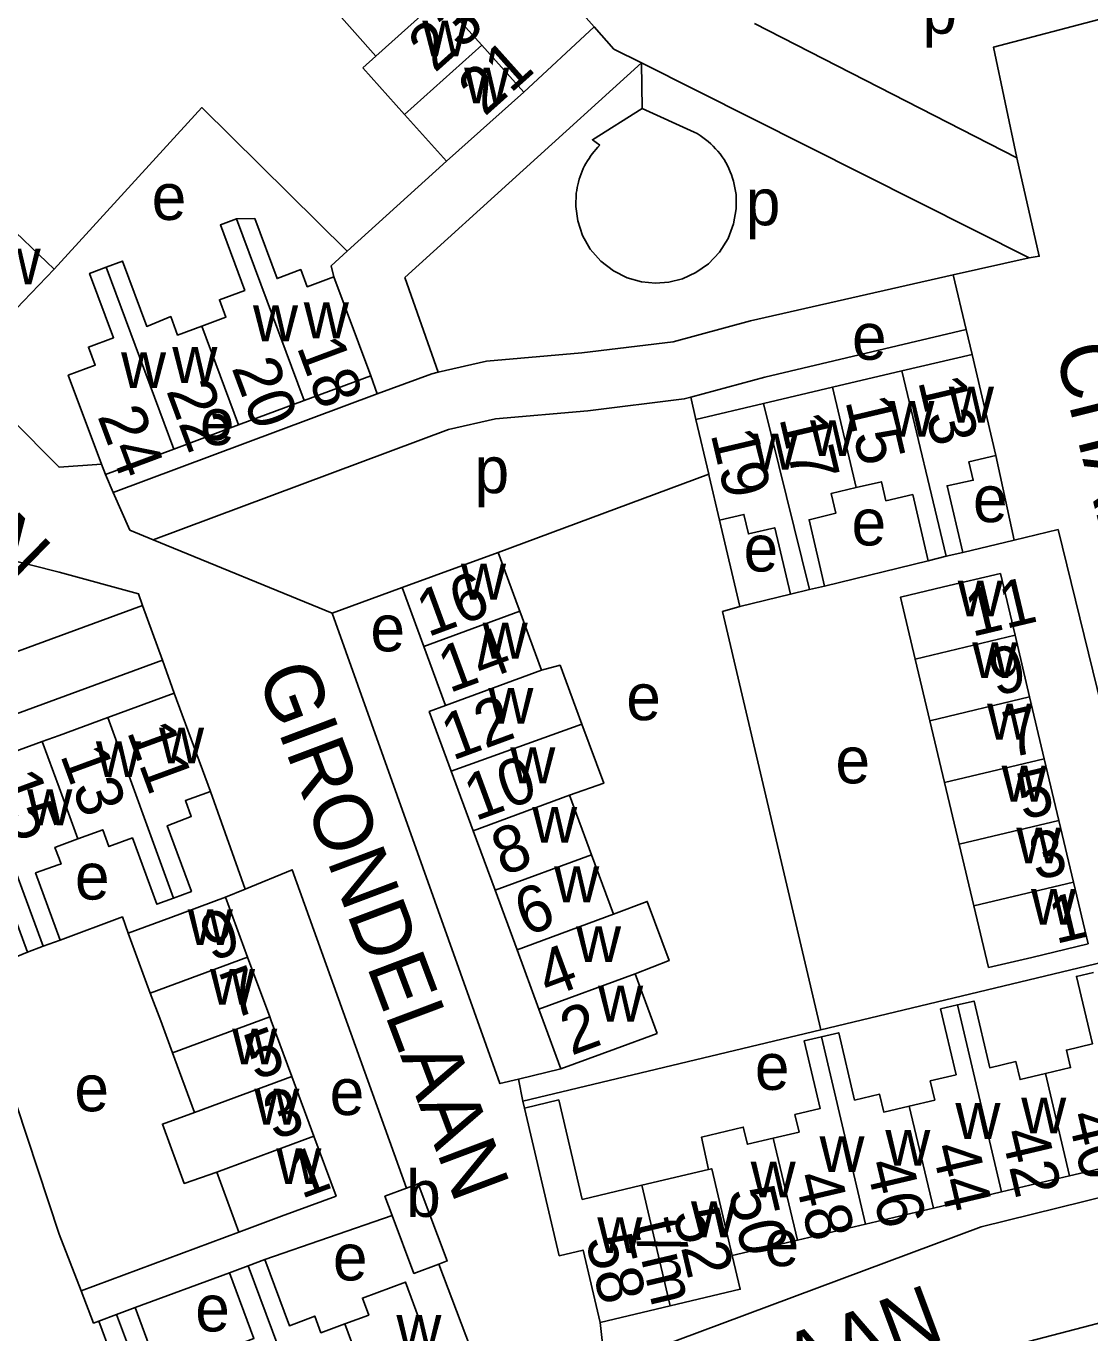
# Model space of a CAD drawing. Extents: x 157768 to 159790, y 387230 to 389604.
# Drawn here: x 159097.2 to 159188.5, y 388723.2 to 388835.4 of the extents above; entities that cross this region are included whole.
import ezdxf

# ---------------------------------------------------------------- set-up
doc = ezdxf.new("R2010")
doc.units = 0
for name, color, linetype in [('BLT_Basislijn', 7, 'Continuous'), ('BLT_Bebouwing', 7, 'Continuous'), ('BLT_Centroide', 7, 'Continuous'), ('BLT_Huisnummer', 7, 'Continuous'), ('BLT_Huisnummer_ tussenligend', 7, 'Continuous'), ('BLT_Huisnummer_reeks', 7, 'Continuous'), ('BLT_Onderverdeling_panden', 7, 'Continuous'), ('BLT_Straatnaam', 7, 'Continuous'), ('BLT_Vlakafsluiter', 7, 'Continuous')]:
    doc.layers.add(name, color=color, linetype=linetype)

msp = doc.modelspace()

# ---------------------------------------------------------------- linework, layer by layer
at = {"layer": 'BLT_Basislijn'}
for p, q in [((159139.9, 388829.78), (159145.94, 388835.4)), ((159145.94, 388835.4), (159147.65, 388833.48)), ((159182.23, 388824.14), (159159.73, 388835.67)), ((159147.65, 388833.48), (159150.03, 388832.28)), ((159150.03, 388832.28), (159129.7, 388813.85)), ((159150.03, 388832.28), (159183.31, 388815.54)), ((159150.06, 388828.37), (159154.55, 388826.35)), ((159133.27, 388823.84), (159124.75, 388816.12)), ((159176.78, 388814.07), (159177.9, 388809.4)), ((159129.7, 388813.85), (159132.55, 388805.72)), ((159177.9, 388809.4), (159178.41, 388807.25)), ((159126.78, 388805.42), (159127.33, 388803.85)), ((159104.66, 388795.39), (159127.33, 388803.85)), ((159154.68, 388801.66), (159154.25, 388803.57)), ((159182.01, 388791.29), (159180.45, 388798.57)), ((159104.66, 388795.39), (159103.98, 388796.93)), ((159155.79, 388796.96), (159137.71, 388790.24)), ((159106.09, 388792.16), (159104.66, 388795.39)), ((159156.71, 388793.01), (159158.46, 388785.59)), ((159108.08, 388791.33), (159106.09, 388792.16)), ((159123.45, 388785.01), (159108.08, 388791.33)), ((159123.45, 388785.01), (159129.46, 388787.21)), ((159158.46, 388785.59), (159156.97, 388785.17)), ((159165.41, 388749.22), (159156.97, 388785.17)), ((159115.98, 388761.31), (159113, 388769.71)), ((159115.98, 388761.31), (159114.29, 388760.61)), ((159092.63, 388753.97), (159097.3, 388755.91)), ((159194.59, 388756.22), (159165.41, 388749.22)), ((159165.41, 388749.22), (159139.84, 388743.09)), ((159143.1, 388745.87), (159139.45, 388744.99)), ((159139.84, 388743.09), (159139.45, 388744.99)), ((159139.84, 388743.09), (159139.96, 388742.5)), ((159101.9, 388726.8), (159115.44, 388731.86)), ((159106.53, 388725.37), (159114.63, 388728.36))]:
    msp.add_line(p, q, dxfattribs=at)
for points in [[(159115.59, 388866.68), (159116.98, 388868.02), (159145.94, 388835.4)], [(159182.23, 388824.14), (159180.25, 388833.65), (159199.41, 388838.71), (159195.8, 388853.99), (159195.38, 388858.13), (159196.26, 388858.38)], [(159124.75, 388816.12), (159112.27, 388828.45), (159099.59, 388814.57)], [(159146.44, 388825.21), (159145.8, 388825.68), (159150.06, 388828.37)], [(159154.55, 388826.35), (159154.8, 388826.21), (159155.04, 388826.06), (159155.28, 388825.89), (159155.51, 388825.72), (159155.74, 388825.54), (159155.96, 388825.34), (159156.17, 388825.13), (159156.38, 388824.92), (159156.57, 388824.7), (159156.76, 388824.47), (159156.93, 388824.23), (159157.1, 388823.98), (159157.25, 388823.73), (159157.39, 388823.47), (159157.52, 388823.21), (159157.64, 388822.94), (159157.74, 388822.67), (159157.84, 388822.4), (159157.92, 388822.13)], [(159144.41, 388821.1), (159144.45, 388821.34), (159144.49, 388821.58), (159144.54, 388821.82), (159144.6, 388822.05), (159144.66, 388822.29), (159144.74, 388822.53), (159144.83, 388822.76), (159144.92, 388822.99), (159145.02, 388823.21), (159145.13, 388823.44), (159145.25, 388823.66), (159145.37, 388823.87), (159145.51, 388824.08), (159145.64, 388824.28), (159145.79, 388824.48), (159145.94, 388824.67), (159146.1, 388824.86), (159146.27, 388825.04), (159146.44, 388825.21)], [(159182.23, 388824.14), (159184.17, 388815.68), (159183.31, 388815.54)], [(159157.92, 388822.13), (159158.14, 388820.98), (159158.15, 388819.74), (159157.93, 388818.45), (159157.45, 388817.19), (159156.72, 388816.03), (159155.78, 388815.04), (159154.69, 388814.27), (159153.53, 388813.75), (159152.36, 388813.45), (159151.22, 388813.36), (159150.02, 388813.48), (159148.79, 388813.83), (159147.6, 388814.42), (159146.52, 388815.26), (159145.62, 388816.29), (159144.96, 388817.47), (159144.54, 388818.71), (159144.37, 388819.94), (159144.41, 388821.1)], [(159124.75, 388816.12), (159123.36, 388814.85), (159123.61, 388813.92)], [(159176.78, 388814.07), (159183.31, 388815.54)], [(159132.55, 388805.72), (159136.71, 388806.66), (159144.89, 388807.37), (159152.73, 388808.34), (159159.37, 388810.14), (159176.78, 388814.07)], [(159154.25, 388803.57), (159160.61, 388805.29), (159177.9, 388809.4)], [(159091.65, 388805.96), (159100.01, 388797.56), (159103.65, 388797.81)], [(159127.33, 388803.85), (159132, 388805.59), (159132.55, 388805.72)], [(159108.08, 388791.33), (159133.43, 388800.79), (159137.49, 388801.7), (159145.42, 388802.4), (159153.69, 388803.42), (159154.25, 388803.57)], [(159081.96, 388797.39), (159082.25, 388797.1), (159088.23, 388791.52), (159100, 388788.53), (159106.82, 388786.69), (159107.18, 388785.69)], [(159182.01, 388791.29), (159185.78, 388792.2), (159193.94, 388758.92), (159194.59, 388756.22)], [(159182.01, 388791.29), (159177.6, 388790.22)], [(159174.64, 388789.52), (159165.74, 388787.35)], [(159162.8, 388786.65), (159158.46, 388785.59)], [(159055.01, 388748.76), (159081.59, 388776.28), (159107.18, 388785.69)], [(159107.18, 388785.69), (159108.88, 388780.99)], [(159123.45, 388785.01), (159137.86, 388744.61), (159139.45, 388744.99)], [(159086.04, 388772.59), (159108.88, 388780.99)], [(159108.88, 388780.99), (159109.9, 388778.16)], [(159129.85, 388735.63), (159120.03, 388762.98), (159115.98, 388761.31)], [(159100.11, 388756.94), (159105.45, 388758.93), (159105.94, 388757.53)], [(159101.9, 388726.8), (159100, 388731.68), (159092.63, 388753.97)], [(159146.47, 388724.1), (159146.89, 388720.24), (159179.17, 388732.29), (159199.12, 388737.23)], [(159117.67, 388729.49), (159128.6, 388733.28)], [(159177.3, 388720.26), (159183.37, 388722.48), (159194.31, 388725.35), (159218.67, 388731.21), (159223.12, 388732.06), (159225.89, 388732.25), (159227.5, 388731.47), (159228.51, 388730.05), (159232.95, 388710.61), (159233.22, 388709.41)], [(159133.4, 388717.7), (159136.44, 388718.96), (159132.62, 388729.1)], [(159101.9, 388726.8), (159102.97, 388724.04), (159103.41, 388724.21)]]:
    msp.add_lwpolyline(points, dxfattribs=at)
at = {"layer": 'BLT_Bebouwing'}
for p, q in [((159136.31, 388833.8), (159132.71, 388837.81)), ((159127.21, 388832.88), (159123.36, 388837.18)), ((159136.31, 388833.8), (159139.9, 388829.78)), ((159126.08, 388831.87), (159127.21, 388832.88)), ((159129.67, 388827.85), (159126.08, 388831.87)), ((159139.9, 388829.78), (159133.27, 388823.84)), ((159099.59, 388814.57), (159095.64, 388818.35)), ((159123.61, 388813.92), (159126.78, 388805.42)), ((159178.41, 388807.25), (159172.36, 388805.83)), ((159180.45, 388798.57), (159178.41, 388807.25)), ((159126.78, 388805.42), (159121.06, 388803.29)), ((159172.36, 388805.83), (159166.43, 388804.43)), ((159166.43, 388804.43), (159160.49, 388803.03)), ((159115.42, 388801.19), (159121.06, 388803.29)), ((159160.49, 388803.03), (159154.68, 388801.66)), ((159154.68, 388801.66), (159155.79, 388796.96)), ((159109.86, 388799.12), (159115.42, 388801.19)), ((159103.98, 388796.93), (159109.86, 388799.12)), ((159103.65, 388797.81), (159103.98, 388796.93)), ((159129.46, 388787.21), (159137.71, 388790.24)), ((159131.33, 388782.15), (159129.46, 388787.21)), ((159139.57, 388785.18), (159141.43, 388780.12)), ((159183.34, 388777.82), (159182.09, 388783.12)), ((159133.2, 388777.08), (159131.33, 388782.15)), ((159174.77, 388775.78), (159173.51, 388781.08)), ((159109.9, 388778.16), (159104.19, 388776.06)), ((159113, 388769.71), (159109.9, 388778.16)), ((159184.6, 388772.52), (159183.34, 388777.82)), ((159176.02, 388770.48), (159174.77, 388775.78)), ((159098.55, 388773.99), (159092.92, 388771.92)), ((159185.86, 388767.21), (159184.6, 388772.52)), ((159135.56, 388766.33), (159133.68, 388771.45)), ((159177.28, 388765.18), (159176.02, 388770.48)), ((159143.83, 388769.38), (159145.71, 388764.26)), ((159187.12, 388761.91), (159185.86, 388767.21)), ((159137.44, 388761.22), (159135.56, 388766.33)), ((159178.54, 388759.88), (159177.28, 388765.18)), ((159145.71, 388764.26), (159147.6, 388759.15)), ((159139.33, 388756.1), (159137.44, 388761.22)), ((159188.38, 388756.61), (159187.12, 388761.91)), ((159116.19, 388755.48), (159114.29, 388760.61)), ((159179.8, 388754.57), (159178.54, 388759.88)), ((159098.63, 388756.4), (159100.11, 388756.94)), ((159107.84, 388752.39), (159105.94, 388757.53)), ((159097.3, 388755.91), (159098.63, 388756.4)), ((159141.21, 388750.99), (159139.33, 388756.1)), ((159118.09, 388750.35), (159116.19, 388755.48)), ((159109.74, 388747.26), (159111.64, 388742.13)), ((159119.99, 388745.22), (159121.89, 388740.09)), ((159139.96, 388742.5), (159142.91, 388743.2)), ((159192.63, 388738.06), (159186.77, 388736.68)), ((159113.54, 388737), (159115.44, 388731.86)), ((159155.76, 388737.22), (159150.04, 388735.87)), ((159186.77, 388736.68), (159180.93, 388735.3)), ((159180.93, 388735.3), (159175.08, 388733.92)), ((159175.08, 388733.92), (159169.26, 388732.54)), ((159169.26, 388732.54), (159163.4, 388731.16)), ((159163.4, 388731.16), (159157.81, 388729.84)), ((159114.63, 388728.36), (159116.25, 388728.96)), ((159116.25, 388728.96), (159117.67, 388729.49)), ((159104.95, 388724.78), (159106.53, 388725.37)), ((159152.48, 388725.52), (159146.47, 388724.1)), ((159103.41, 388724.21), (159104.95, 388724.78))]:
    msp.add_line(p, q, dxfattribs=at)
for points in [[(159133.27, 388823.84), (159129.93, 388827.56), (159129.67, 388827.85)], [(159112.26, 388809.68), (159114.33, 388810.46), (159113.78, 388811.94), (159115.95, 388812.75), (159113.86, 388818.37), (159115.24, 388818.89)], [(159115.24, 388818.89), (159116.81, 388818.92), (159118.73, 388813.76), (159120.76, 388814.54), (159121.31, 388813.06), (159123.61, 388813.92)], [(159112.26, 388809.68), (159110.18, 388808.91), (159109.59, 388810.5), (159107.53, 388809.65), (159105.44, 388815.26), (159104.04, 388814.74)], [(159093.49, 388808.2), (159096.95, 388811.81), (159099.59, 388814.57)], [(159104.04, 388814.74), (159102.63, 388814.21), (159104.69, 388808.68), (159102.53, 388807.87), (159103.11, 388806.32), (159100.8, 388805.46), (159103.65, 388797.81)], [(159177.6, 388790.22), (159176.25, 388795.96), (159178.5, 388796.43), (159178.13, 388798.03), (159180.45, 388798.57)], [(159155.79, 388796.96), (159155.82, 388796.8), (159156.71, 388793.01)], [(159168.46, 388795.8), (159170.62, 388796.31), (159171.01, 388794.67), (159173.3, 388795.21), (159174.64, 388789.52)], [(159165.74, 388787.35), (159164.4, 388793.05), (159166.7, 388793.6), (159166.3, 388795.29), (159168.46, 388795.8)], [(159156.71, 388793.01), (159158.81, 388793.5), (159159.2, 388791.83), (159161.46, 388792.36), (159162.8, 388786.65)], [(159137.71, 388790.24), (159139.43, 388785.55), (159139.57, 388785.18)], [(159174.64, 388789.52), (159176.17, 388789.91)], [(159176.17, 388789.91), (159177.6, 388790.22)], [(159173.51, 388781.08), (159172.25, 388786.39), (159175.96, 388787.27), (159180.83, 388788.42), (159182.09, 388783.12)], [(159162.8, 388786.65), (159164.44, 388787.04)], [(159164.44, 388787.04), (159165.74, 388787.35)], [(159141.43, 388780.12), (159143.03, 388780.55), (159144.9, 388775.48)], [(159133.68, 388771.45), (159131.79, 388776.56), (159133.2, 388777.08)], [(159104.19, 388776.06), (159100, 388774.52), (159098.55, 388773.99)], [(159144.9, 388775.48), (159146.77, 388770.41), (159143.83, 388769.38)], [(159109.83, 388760.55), (159111.37, 388761.11), (159109.29, 388766.76), (159111.36, 388767.56), (159110.85, 388768.92), (159113, 388769.71)], [(159100, 388763.94), (159099.65, 388764.9), (159100, 388765.03), (159101.63, 388765.62)], [(159101.63, 388765.62), (159103.76, 388766.41), (159104.29, 388764.97), (159106.31, 388765.71), (159108.39, 388760.02), (159109.83, 388760.55)], [(159100.11, 388756.94), (159097.99, 388762.7), (159100, 388763.43)], [(159100, 388763.43), (159100.18, 388763.46), (159100, 388763.94)], [(159090.17, 388761.42), (159092.55, 388762.3), (159093.06, 388760.9), (159095.18, 388761.67), (159097.3, 388755.91)], [(159105.94, 388757.53), (159109.6, 388758.88), (159114.29, 388760.61)], [(159147.6, 388759.15), (159150.51, 388760.26), (159152.38, 388755.18), (159149.48, 388754.03)], [(159188.38, 388756.61), (159183.52, 388755.45), (159179.8, 388754.57)], [(159149.48, 388754.03), (159150.96, 388750), (159151.36, 388748.92)], [(159188.84, 388754.16), (159187.36, 388753.81), (159188.73, 388748.02), (159186.5, 388747.49), (159186.86, 388745.98), (159184.7, 388745.47)], [(159109.74, 388747.26), (159108.73, 388750), (159107.84, 388752.39)], [(159177.16, 388751.36), (159175.7, 388751.02), (159177.03, 388745.37), (159174.81, 388744.84), (159175.2, 388743.19), (159173.01, 388742.67)], [(159184.7, 388745.47), (159182.53, 388744.96), (159182.17, 388746.5), (159179.92, 388745.97), (159178.57, 388751.7), (159177.16, 388751.36)], [(159119.99, 388745.22), (159118.22, 388750), (159118.09, 388750.35)], [(159143.1, 388745.87), (159141.58, 388750), (159141.21, 388750.99)], [(159143.1, 388745.87), (159147.79, 388747.6), (159151.36, 388748.92)], [(159173.01, 388742.67), (159170.82, 388742.16), (159170.46, 388743.7), (159168.31, 388743.19), (159166.95, 388748.97), (159165.48, 388748.62)], [(159165.48, 388748.62), (159163.98, 388748.27), (159165.35, 388742.46), (159163.19, 388741.95), (159163.54, 388740.45), (159161.33, 388739.92)], [(159150.04, 388735.87), (159144.93, 388734.66), (159142.91, 388743.2)], [(159111.64, 388742.13), (159108.88, 388741.13), (159110.76, 388736.04), (159113.54, 388737)], [(159146.47, 388724.1), (159145, 388730.31), (159142.95, 388729.82), (159139.96, 388742.5)], [(159115.44, 388731.86), (159119.1, 388733.22), (159123.79, 388734.95), (159121.89, 388740.09)], [(159161.33, 388739.92), (159159.11, 388739.4), (159158.76, 388740.87), (159155.17, 388740.02), (159155.76, 388737.22)], [(159128.6, 388733.28), (159127.98, 388734.93), (159129.85, 388735.63)], [(159129.85, 388735.63), (159130.84, 388736), (159133.33, 388729.37), (159132.62, 388729.1)], [(159132.62, 388729.1), (159130.47, 388728.3), (159128.6, 388733.28)], [(159157.81, 388729.84), (159158.49, 388726.94), (159152.48, 388725.52)], [(159124.54, 388723.96), (159122.49, 388723.2), (159121.96, 388724.64), (159119.78, 388723.81), (159117.67, 388729.49)], [(159114.63, 388728.36), (159116.73, 388722.7), (159114.84, 388722), (159115.38, 388720.56), (159113.31, 388719.8)], [(159133.4, 388717.7), (159129.75, 388727.56), (159126.05, 388726.18), (159126.59, 388724.72), (159124.54, 388723.96)], [(159113.31, 388719.8), (159111.24, 388719.03), (159110.73, 388720.41), (159108.66, 388719.62), (159106.53, 388725.37)], [(159103.41, 388724.21), (159105.54, 388718.48), (159103.73, 388717.8), (159104.21, 388716.49), (159100, 388714.93), (159093.45, 388712.5), (159091.39, 388715.41)]]:
    msp.add_lwpolyline(points, dxfattribs=at)
at = {"layer": 'BLT_Onderverdeling_panden'}
for p, q in [((159127.21, 388832.88), (159132.71, 388837.81)), ((159136.31, 388833.8), (159129.67, 388827.85)), ((159115.24, 388818.89), (159121.06, 388803.29)), ((159104.04, 388814.74), (159109.86, 388799.12)), ((159112.26, 388809.68), (159115.42, 388801.19)), ((159176.17, 388789.91), (159172.36, 388805.83)), ((159168.46, 388795.8), (159166.43, 388804.43)), ((159164.44, 388787.04), (159160.49, 388803.03)), ((159131.33, 388782.15), (159139.57, 388785.18)), ((159173.51, 388781.08), (159182.09, 388783.12)), ((159133.2, 388777.08), (159141.43, 388780.12)), ((159174.77, 388775.78), (159183.34, 388777.82)), ((159109.83, 388760.55), (159104.19, 388776.06)), ((159133.68, 388771.45), (159144.9, 388775.48)), ((159176.02, 388770.48), (159184.6, 388772.52)), ((159098.63, 388756.4), (159092.92, 388771.92)), ((159135.56, 388766.33), (159143.83, 388769.38)), ((159177.28, 388765.18), (159185.86, 388767.21)), ((159137.44, 388761.22), (159145.71, 388764.26)), ((159178.54, 388759.88), (159187.12, 388761.91)), ((159139.33, 388756.1), (159147.6, 388759.15)), ((159107.84, 388752.39), (159116.19, 388755.48)), ((159141.21, 388750.99), (159149.48, 388754.03)), ((159177.16, 388751.36), (159180.93, 388735.3)), ((159109.74, 388747.26), (159118.09, 388750.35)), ((159165.48, 388748.62), (159169.26, 388732.54)), ((159184.7, 388745.47), (159186.77, 388736.68)), ((159111.64, 388742.13), (159119.99, 388745.22)), ((159173.01, 388742.67), (159175.08, 388733.92)), ((159113.54, 388737), (159121.89, 388740.09)), ((159161.33, 388739.92), (159163.4, 388731.16)), ((159152.48, 388725.52), (159150.04, 388735.87)), ((159116.25, 388728.96), (159122.03, 388713.48)), ((159104.95, 388724.78), (159110.7, 388709.28)), ((159124.54, 388723.96), (159127.65, 388715.56))]:
    msp.add_line(p, q, dxfattribs=at)
for points in [[(159101.63, 388765.62), (159100, 388770.05), (159098.55, 388773.99)], [(159157.81, 388729.84), (159156.05, 388737.29), (159155.76, 388737.22)]]:
    msp.add_lwpolyline(points, dxfattribs=at)
at = {"layer": 'BLT_Vlakafsluiter'}
msp.add_line((159150.06, 388828.37), (159150.03, 388832.28), dxfattribs=at)

# ---------------------------------------------------------------- texts
at = {"layer": 'BLT_Centroide'}
for s, p in [('p', (159174.13, 388834.8)), ('w', (159131.2, 388832.84)), ('w', (159134.79, 388828.81)), ('e', (159107.96, 388818.8)), ('p', (159158.97, 388818.34)), ('w', (159094.56, 388813.27)), ('w', (159121.02, 388808.64)), ('w', (159116.66, 388808.38)), ('e', (159168.09, 388806.79)), ('w', (159105.33, 388804.36)), ('w', (159109.73, 388804.8)), ('w', (159176.41, 388801.39)), ('w', (159171.3, 388800.17)), ('e', (159112.1, 388799.46)), ('w', (159164.48, 388798.52)), ('w', (159159.56, 388797.36)), ('p', (159135.68, 388795.33)), ('e', (159178.48, 388792.84)), ('e', (159168.05, 388790.84)), ('e', (159158.78, 388788.6)), ('w', (159134.52, 388786.19)), ('w', (159177.17, 388784.75)), ('e', (159126.74, 388781.74)), ('w', (159136.38, 388781.12)), ('w', (159178.42, 388779.44)), ('w', (159136.87, 388775.53)), ('e', (159148.71, 388775.83)), ('w', (159179.69, 388774.16)), ('w', (159108.59, 388772.12)), ('w', (159103.17, 388770.94)), ('w', (159138.75, 388770.41)), ('e', (159166.67, 388770.4)), ('w', (159180.94, 388768.84)), ('w', (159097.27, 388766.8)), ('w', (159140.63, 388765.31)), ('w', (159182.2, 388763.53)), ('e', (159101.37, 388760.42)), ('w', (159142.52, 388760.19)), ('w', (159183.46, 388758.25)), ('w', (159111.06, 388756.5)), ('w', (159144.4, 388755.06)), ('w', (159112.97, 388751.38)), ('w', (159146.29, 388749.94)), ('w', (159114.87, 388746.25)), ('e', (159159.75, 388744.07)), ('e', (159101.32, 388742.23)), ('e', (159123.24, 388741.91)), ('w', (159116.77, 388741.09)), ('w', (159182.62, 388740.33)), ('w', (159176.97, 388739.86)), ('w', (159165.3, 388737.02)), ('w', (159170.95, 388737.56)), ('w', (159118.66, 388735.97)), ('w', (159159.39, 388734.84)), ('b', (159129.81, 388733.16)), ('w', (159154.27, 388731.41)), ('w', (159146.22, 388730.06)), ('e', (159160.58, 388728.93)), ('e', (159123.52, 388727.7)), ('e', (159111.7, 388723.32)), ('w', (159128.97, 388721.67))]:
    msp.add_text(s, height=4, dxfattribs=at).set_placement(p)
at = {"layer": 'BLT_Huisnummer'}
for s, rotation, p in [('21', 41.86, (159136.54, 388827.62)), ('18', 290.4355, (159120.38, 388807.91)), ('13', 283.2551, (159173.75, 388804.96)), ('24', 290.4339, (159103.27, 388801.96)), ('19', 283.2497, (159155.94, 388800.42)), ('16', 20.2188, (159131.66, 388782.94)), ('11', 13.3522, (159178.38, 388782.97)), ('11', 290.162, (159105.8, 388774.86)), ('10', 20.2181, (159135.74, 388767.13)), ('5', 13.3537, (159182.77, 388767.25)), ('6', 20.2181, (159140.07, 388757.23)), ('1', 13.3468, (159185.57, 388756.59)), ('9', 20.3158, (159113.1, 388755.06)), ('2', 20.2181, (159143.99, 388746.99)), ('5', 20.312, (159116.87, 388744.85)), ('42', 283.2942, (159180.87, 388740.39)), ('1', 20.3052, (159120.8, 388734.68)), ('46', 283.2825, (159169.26, 388737.73)), ('50', 283.2825, (159157.43, 388735.34))]:
    msp.add_text(s, height=4, rotation=rotation, dxfattribs=at).set_placement(p)
at = {"layer": 'BLT_Huisnummer_ tussenligend'}
for s, rotation, p in [('23', 41.86, (159132.26, 388831.37)), ('20', 290.4355, (159114.79, 388806.11)), ('22', 290.4355, (159109.18, 388804.14)), ('15', 283.2551, (159167.5, 388803.26)), ('17', 283.2551, (159161.83, 388801.78)), ('14', 20.2181, (159133.51, 388778.13)), ('9', 13.3537, (159180.41, 388777.89)), ('12', 20.2181, (159133.78, 388772.33)), ('7', 13.3537, (159181.64, 388772.57)), ('13', 290.162, (159100.07, 388772.84)), ('15', 290.162, (159094.35, 388770.73)), ('8', 20.2181, (159138.1, 388762.42)), ('3', 13.3468, (159183.9, 388762.05)), ('4', 20.2181, (159142, 388751.94)), ('7', 20.3052, (159114.92, 388750.1)), ('3', 20.3052, (159118.52, 388739.71)), ('40', 283.2876, (159186.57, 388741.88)), ('44', 283.2942, (159174.9, 388739.15)), ('48', 283.2825, (159163.12, 388736.64))]:
    msp.add_text(s, height=4, rotation=rotation, dxfattribs=at).set_placement(p)
at = {"layer": 'BLT_Huisnummer_reeks'}
for s, rotation, p in [('t/m', 283.2869, (159149.27, 388732.53)), ('52', 283.2871, (159152.7, 388733.47)), ('58', 283.2869, (159145.2, 388731.22))]:
    msp.add_text(s, height=4, rotation=rotation, dxfattribs=at).set_placement(p)
at = {"layer": 'BLT_Straatnaam'}
for s, rotation, p in [('GIRONDELAAN', 315.621, (159061.36, 388821.15)), ('CHARENTELAAN', 284.1196, (159185.51, 388807.65)), ('GIRONDELAAN', 290.621, (159116.97, 388779.74)), ('CALAISLAAN', 20.5058, (159137.56, 388708.3))]:
    msp.add_text(s, height=5, rotation=rotation, dxfattribs=at).set_placement(p)

doc.saveas('drawing.dxf')
